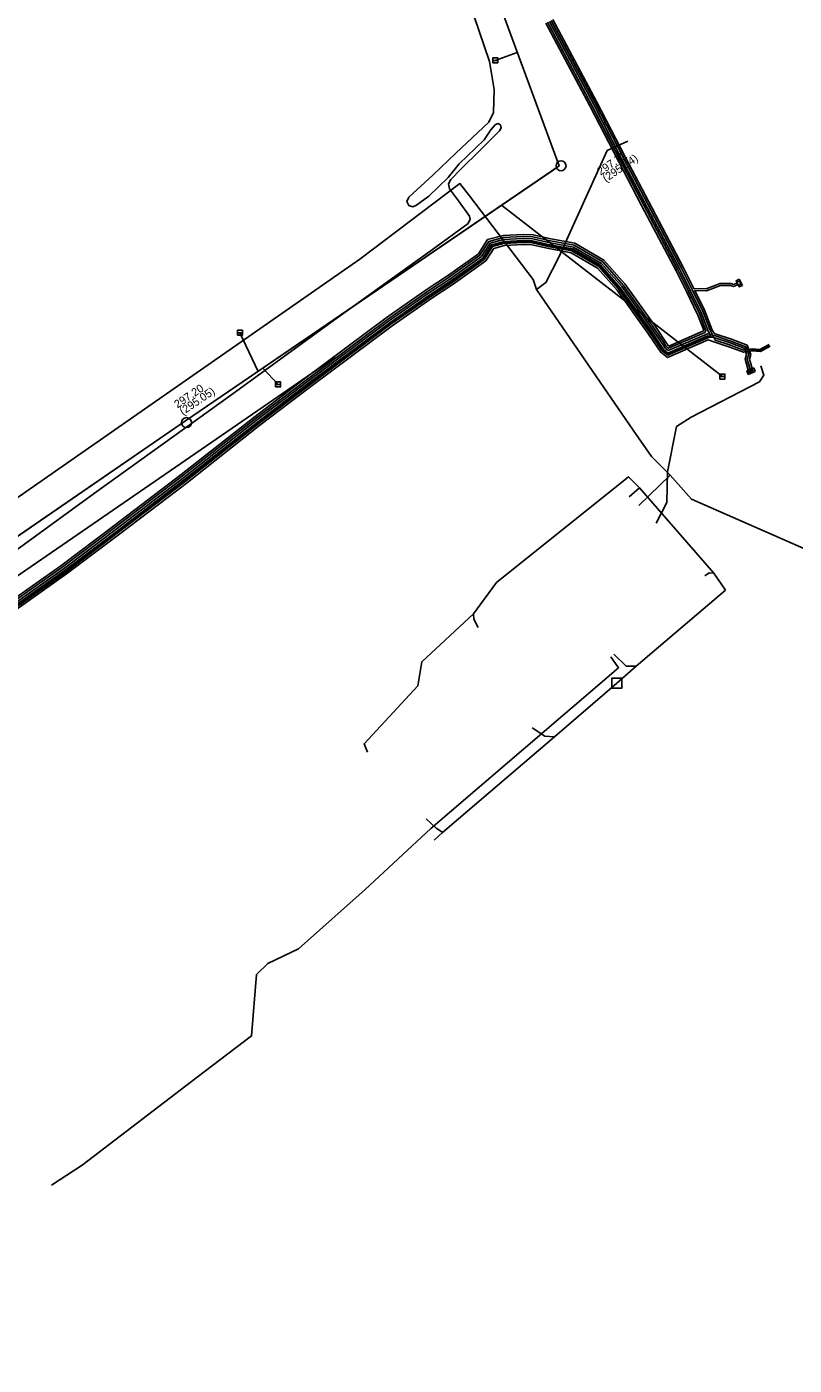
# Model space of a CAD drawing. Extents: x -600391 to -599491, y -1160176 to -1159402.
# Drawn here: x -599721.4 to -599644.7, y -1159814.7 to -1159680.9 of the extents above; entities that cross this region are included whole.
import ezdxf

# ---------------------------------------------------------------- set-up
doc = ezdxf.new("R2010")
doc.units = 0
for name, color, linetype in [('28', 7, 'Continuous'), ('31', 7, 'Continuous'), ('Vrstva 1', 7, 'Continuous'), ('Vrstva 11', 7, 'Continuous'), ('Vrstva 13', 7, 'Continuous'), ('Vrstva 19', 7, 'Continuous'), ('Vrstva 3', 7, 'Continuous'), ('Vrstva 4', 7, 'Continuous'), ('Vrstva 42', 7, 'Continuous'), ('Vrstva 43', 7, 'Continuous'), ('Vrstva 44', 7, 'Continuous'), ('Vrstva 58', 7, 'Continuous'), ('Vrstva 9', 7, 'Continuous')]:
    doc.layers.add(name, color=color, linetype=linetype)

# ---------------------------------------------------------------- blocks, each defined once
blk = doc.blocks.new('NN630')
at = {"layer": '31'}
for points in [[(0, -0.7), (-0.7, 0)], [(-0.7, -0.7), (-0.7, 0), (0.7, 0), (0.7, -0.7)], [(-0.7, -0.7), (0.7, -0.7)], [(0, -0.7), (0.7, 0)]]:
    blk.add_lwpolyline(points, dxfattribs=at)
blk = doc.blocks.new('NN620')
at = {"layer": '28'}
for points in [[(0.75, 0), (-0.75, 0)], [(-0.75, 0), (-0.75, -0.75)], [(0.75, -0.75), (0.75, 0)], [(-0.75, -0.75), (0.75, -0.75)], [(0.37, -0.18), (-0.38, -0.18)], [(-0.38, -0.18), (-0.38, -0.56)], [(-0.38, -0.56), (0.37, -0.56)], [(0.32, -0.23), (-0.33, -0.23)], [(-0.33, -0.23), (-0.33, -0.51)], [(-0.33, -0.51), (0.32, -0.51)], [(0.27, -0.27), (-0.28, -0.27)], [(-0.28, -0.27), (-0.28, -0.46)], [(-0.28, -0.46), (0.27, -0.46)], [(0.23, -0.32), (-0.23, -0.32)], [(-0.23, -0.32), (-0.23, -0.42)], [(-0.23, -0.42), (0.23, -0.42)], [(-0.19, -0.37), (0.19, -0.37)], [(0.23, -0.42), (0.23, -0.32)], [(0.27, -0.46), (0.27, -0.27)], [(0.32, -0.51), (0.32, -0.23)], [(0.37, -0.56), (0.37, -0.18)]]:
    blk.add_lwpolyline(points, dxfattribs=at)

msp = doc.modelspace()

# ---------------------------------------------------------------- linework, layer by layer
at = {"layer": 'Vrstva 1'}
for p, q in [((-599674.58, -1159684.31), (-599672.38, -1159683.53)), ((-599651.88, -1159715.91), (-599673.97, -1159698.78)), ((-599700.11, -1159711.53), (-599698.3, -1159715.39)), ((-599696.3, -1159716.69), (-599697.81, -1159715.05))]:
    msp.add_line(p, q, dxfattribs=at)
for points in [[(-599733.6, -1159557.62), (-599719.6, -1159585.05), (-599698.44, -1159625.81), (-599676.83, -1159671.44), (-599668.21, -1159694.85), (-599705.56, -1159720.34), (-599743.19, -1159746.17), (-599779.24, -1159770.44), (-599816.43, -1159796.74)], [(-599668.21, -1159694.85), (-599676.83, -1159671.44)], [(-599672.38, -1159683.53), (-599674.58, -1159684.31)], [(-599705.56, -1159720.34), (-599668.91, -1159695.33), (-599668.21, -1159694.85)], [(-599673.97, -1159698.78), (-599651.88, -1159715.91)], [(-599698.3, -1159715.39), (-599700.11, -1159711.53)], [(-599690.59, -1159713.98), (-599695.76, -1159717.54), (-599765.8, -1159765.71)], [(-599697.81, -1159715.05), (-599696.3, -1159716.69)], [(-599743.19, -1159746.17), (-599725.14, -1159733.78), (-599705.56, -1159720.34)]]:
    msp.add_lwpolyline(points, dxfattribs=at)
at = {"layer": 'Vrstva 11'}
msp.add_lwpolyline([(-599662.92, -1159747.03), (-599661.92, -1159747.03), (-599661.92, -1159746.03), (-599662.92, -1159746.03)], close=True, dxfattribs=at)
at = {"layer": 'Vrstva 13'}
msp.add_lwpolyline([(-599718.93, -1159796.73), (-599715.87, -1159794.72), (-599704.39, -1159785.91), (-599698.94, -1159781.8), (-599698.46, -1159775.66), (-599697.31, -1159774.56), (-599694.25, -1159773.1), (-599687.6, -1159767.16), (-599681.04, -1159761.07), (-599662.26, -1159745), (-599663.05, -1159743.91)], dxfattribs=at)
at = {"layer": 'Vrstva 19'}
for points in [[(-599670.46, -1159707.2), (-599669.53, -1159706.51), (-599668.23, -1159703.97), (-599663.4, -1159693.32), (-599661.35, -1159692.39)], [(-599848.5, -1159814.71), (-599774.58, -1159764.38), (-599688.11, -1159704.16), (-599678.12, -1159696.61), (-599677.16, -1159697.83), (-599670.8, -1159706.19), (-599670.46, -1159707.2), (-599660.79, -1159721.25), (-599658.97, -1159723.88), (-599657.1, -1159725.77), (-599654.96, -1159728.17), (-599642.68, -1159733.56)], [(-599657.1, -1159725.77), (-599660.23, -1159728.79)]]:
    msp.add_lwpolyline(points, dxfattribs=at)
at = {"layer": 'Vrstva 3'}
for p, q in [((-599674.83, -1159684.31), (-599674.33, -1159684.31)), ((-599700.36, -1159711.53), (-599699.86, -1159711.53)), ((-599652.13, -1159715.91), (-599651.63, -1159715.91)), ((-599696.55, -1159716.69), (-599696.05, -1159716.69))]:
    msp.add_line(p, q, dxfattribs=at)
for points in [[(-599674.83, -1159684.56), (-599674.33, -1159684.56), (-599674.33, -1159684.06), (-599674.83, -1159684.06)], [(-599700.36, -1159711.78), (-599699.86, -1159711.78), (-599699.86, -1159711.28), (-599700.36, -1159711.28)], [(-599696.55, -1159716.94), (-599696.05, -1159716.94), (-599696.05, -1159716.44), (-599696.55, -1159716.44)], [(-599652.13, -1159716.16), (-599651.63, -1159716.16), (-599651.63, -1159715.66), (-599652.13, -1159715.66)]]:
    msp.add_lwpolyline(points, close=True, dxfattribs=at)
for centre in [(-599668.01, -1159694.84), (-599705.45, -1159720.51)]:
    msp.add_circle(centre, 0.5, dxfattribs=at)
at = {"layer": 'Vrstva 42'}
for points in [[(-599648.91, -1159715.11), (-599649.18, -1159714.18), (-599649.04, -1159713.69), (-599649.4, -1159712.76), (-599650.98, -1159712.16), (-599652.61, -1159711.62), (-599652.72, -1159711.58), (-599652.9, -1159711.27), (-599653.67, -1159709.28), (-599654.64, -1159707.3), (-599653.47, -1159707.32), (-599652.07, -1159706.81), (-599651.08, -1159706.81), (-599650.77, -1159706.91), (-599650.44, -1159706.78), (-599650.36, -1159706.64), (-599650.53, -1159706.6), (-599650.77, -1159706.69), (-599651.05, -1159706.61), (-599652.11, -1159706.61), (-599653.51, -1159707.12), (-599654.74, -1159707.1), (-599655.8, -1159704.97), (-599659.25, -1159698.43), (-599661.57, -1159694.02), (-599664.42, -1159688.47), (-599668.82, -1159680.23)], [(-599681.25, -1159707.56), (-599679.14, -1159706.18), (-599675.97, -1159703.92), (-599675.11, -1159702.57), (-599673.75, -1159702.21), (-599671.79, -1159702.12), (-599670.84, -1159702.14), (-599669.1, -1159702.54), (-599666.77, -1159702.96), (-599663.98, -1159704.6), (-599661.95, -1159706.9), (-599658.83, -1159711.24), (-599657.85, -1159712.7), (-599657.61, -1159713.06), (-599657.29, -1159713.31), (-599653.38, -1159711.62), (-599652.67, -1159711.81), (-599651.04, -1159712.35), (-599649.54, -1159712.92), (-599649.25, -1159713.7), (-599649.39, -1159714.18), (-599649.1, -1159715.19)], [(-599681.14, -1159707.73), (-599679.03, -1159706.35), (-599675.82, -1159704.06), (-599674.98, -1159702.74), (-599673.71, -1159702.41), (-599671.79, -1159702.32), (-599670.87, -1159702.34), (-599669.14, -1159702.73), (-599666.84, -1159703.15), (-599664.11, -1159704.75), (-599662.1, -1159707.03), (-599659, -1159711.35), (-599658.02, -1159712.81), (-599657.76, -1159713.2), (-599657.32, -1159713.55), (-599653.36, -1159711.83), (-599652.73, -1159712), (-599651.11, -1159712.54), (-599649.69, -1159713.08), (-599649.46, -1159713.71), (-599649.6, -1159714.18), (-599649.29, -1159715.27)], [(-599725.64, -1159740.68), (-599717.79, -1159735.15), (-599712.48, -1159731.15), (-599705.72, -1159726), (-599698.47, -1159720.29), (-599693.37, -1159716.41), (-599685.25, -1159710.36), (-599681.25, -1159707.56)], [(-599725.53, -1159740.85), (-599717.67, -1159735.31), (-599712.36, -1159731.31), (-599705.6, -1159726.16), (-599698.35, -1159720.45), (-599693.25, -1159716.57), (-599685.13, -1159710.52), (-599681.14, -1159707.73)], [(-599648.05, -1159714.83), (-599647.74, -1159715.76), (-599648.18, -1159716.44), (-599655.01, -1159719.95), (-599656.47, -1159720.9), (-599657.38, -1159725.43), (-599657.42, -1159728.5), (-599658.5, -1159730.54)]]:
    msp.add_lwpolyline(points, dxfattribs=at)
at = {"layer": 'Vrstva 44'}
for points in [[(-599655.82, -1159705.39), (-599655.98, -1159705.06), (-599661.75, -1159694.11), (-599664.6, -1159688.56), (-599669, -1159680.32)], [(-599656, -1159705.48), (-599656.16, -1159705.15), (-599661.93, -1159694.2), (-599664.78, -1159688.65), (-599669.18, -1159680.41)], [(-599725.47, -1159740.93), (-599717.61, -1159735.39), (-599712.3, -1159731.39), (-599705.54, -1159726.24), (-599698.29, -1159720.53), (-599693.19, -1159716.65), (-599685.07, -1159710.6), (-599681.09, -1159707.81), (-599678.97, -1159706.43), (-599675.75, -1159704.13), (-599674.92, -1159702.83), (-599673.7, -1159702.51), (-599671.79, -1159702.42), (-599670.88, -1159702.44), (-599669.16, -1159702.83), (-599666.88, -1159703.25), (-599664.17, -1159704.83), (-599662.18, -1159707.09), (-599659.08, -1159711.41), (-599658.1, -1159712.87), (-599657.83, -1159713.27), (-599657.33, -1159713.66), (-599653.35, -1159711.93), (-599652.73, -1159712)], [(-599725.41, -1159741.01), (-599717.55, -1159735.47), (-599712.24, -1159731.47), (-599705.48, -1159726.32), (-599698.23, -1159720.61), (-599693.13, -1159716.73), (-599685.01, -1159710.68), (-599681.03, -1159707.89), (-599678.91, -1159706.51), (-599675.68, -1159704.2), (-599674.86, -1159702.92), (-599673.69, -1159702.61), (-599671.79, -1159702.52), (-599670.89, -1159702.54), (-599669.18, -1159702.93), (-599666.92, -1159703.34), (-599664.23, -1159704.91), (-599662.26, -1159707.15), (-599659.16, -1159711.47), (-599658.18, -1159712.93), (-599657.9, -1159713.34), (-599657.35, -1159713.78), (-599653.34, -1159712.03), (-599652.99, -1159711.94), (-599653.26, -1159711.43), (-599654.03, -1159709.44), (-599655.09, -1159707.29), (-599656, -1159705.48)], [(-599725.3, -1159741.18), (-599717.43, -1159735.63), (-599712.12, -1159731.63), (-599705.36, -1159726.48), (-599698.11, -1159720.77), (-599693.01, -1159716.89), (-599684.89, -1159710.84), (-599680.92, -1159708.06), (-599678.8, -1159706.68), (-599675.53, -1159704.34), (-599674.73, -1159703.09), (-599673.65, -1159702.81), (-599671.79, -1159702.72), (-599670.92, -1159702.74), (-599669.22, -1159703.12), (-599666.99, -1159703.54), (-599664.36, -1159705.06), (-599662.41, -1159707.28), (-599659.33, -1159711.58), (-599658.35, -1159713.04), (-599658.05, -1159713.48), (-599657.37, -1159714.01), (-599653.3, -1159712.24), (-599652.73, -1159712.42), (-599651.24, -1159712.92), (-599649.76, -1159713.48), (-599648.88, -1159713.32), (-599648.09, -1159713.39), (-599647.11, -1159712.87)], [(-599647.21, -1159712.69), (-599648.13, -1159713.19), (-599648.9, -1159713.12), (-599649.77, -1159713.26), (-599651.18, -1159712.73), (-599652.59, -1159712.26), (-599653.08, -1159711.35), (-599653.85, -1159709.36), (-599654.91, -1159707.2), (-599655.82, -1159705.39)], [(-599652.73, -1159712), (-599651.11, -1159712.54), (-599649.45, -1159713.17), (-599648.11, -1159713.29), (-599647.16, -1159712.78)]]:
    msp.add_lwpolyline(points, dxfattribs=at)
at = {"layer": 'Vrstva 58'}
for points in [[(-599677.23, -1159678.36), (-599675.17, -1159684.41), (-599674.71, -1159687.2), (-599674.76, -1159689.53), (-599675.23, -1159690.47), (-599678.54, -1159693.58), (-599680.81, -1159695.76), (-599683.24, -1159697.99), (-599683.41, -1159698.4), (-599683.24, -1159698.82), (-599682.83, -1159698.94), (-599682.46, -1159698.76), (-599681.21, -1159697.87), (-599679.3, -1159696), (-599678.21, -1159694.65), (-599675.7, -1159692.24), (-599675.03, -1159691.25), (-599674.61, -1159690.73), (-599674.32, -1159690.62), (-599674.05, -1159690.76), (-599674, -1159691.05), (-599674.16, -1159691.36), (-599676.1, -1159693.28), (-599678.02, -1159695.19), (-599679.04, -1159696.2), (-599679.25, -1159696.64), (-599679.17, -1159697.14), (-599678.27, -1159698.35), (-599677.17, -1159699.88), (-599677.09, -1159700.19), (-599677.29, -1159700.6), (-599680.87, -1159703.2), (-599685.34, -1159706.4), (-599691.26, -1159710.68), (-599700.93, -1159717.68), (-599714.66, -1159727.57), (-599733.33, -1159741.14)], [(-599654.39, -1159709.62), (-599655.45, -1159707.47), (-599656.51, -1159705.33), (-599659.96, -1159698.8), (-599662.28, -1159694.39), (-599665.13, -1159688.84), (-599669.53, -1159680.59)], [(-599654.21, -1159709.54), (-599655.27, -1159707.38), (-599656.34, -1159705.24), (-599659.78, -1159698.71), (-599662.11, -1159694.29), (-599664.95, -1159688.75), (-599669.36, -1159680.5)], [(-599657.52, -1159712.48), (-599658.5, -1159711.01), (-599661.63, -1159706.65), (-599663.72, -1159704.28), (-599666.63, -1159702.58), (-599669.02, -1159702.14), (-599670.79, -1159701.74), (-599671.8, -1159701.72), (-599673.81, -1159701.81), (-599675.36, -1159702.22), (-599676.27, -1159703.64), (-599679.36, -1159705.85), (-599681.48, -1159707.23), (-599685.48, -1159710.03), (-599693.61, -1159716.09), (-599698.72, -1159719.98), (-599705.97, -1159725.69), (-599712.72, -1159730.83), (-599718.02, -1159734.82), (-599725.87, -1159740.36)], [(-599657.68, -1159712.59), (-599658.67, -1159711.12), (-599661.79, -1159706.78), (-599663.85, -1159704.44), (-599666.7, -1159702.77), (-599669.06, -1159702.34), (-599670.82, -1159701.94), (-599671.8, -1159701.92), (-599673.78, -1159702.01), (-599675.24, -1159702.4), (-599676.12, -1159703.78), (-599679.25, -1159706.02), (-599681.37, -1159707.4), (-599685.36, -1159710.19), (-599693.49, -1159716.25), (-599698.6, -1159720.13), (-599705.85, -1159725.84), (-599712.6, -1159730.99), (-599717.9, -1159734.99), (-599725.76, -1159740.52)], [(-599657.69, -1159712.59), (-599657.46, -1159712.92), (-599657.26, -1159713.08), (-599653.63, -1159711.51), (-599653.53, -1159711.29), (-599654.21, -1159709.54)], [(-599654.4, -1159709.61), (-599653.75, -1159711.28), (-599653.78, -1159711.35), (-599657.23, -1159712.85), (-599657.31, -1159712.79), (-599657.52, -1159712.48)]]:
    msp.add_lwpolyline(points, dxfattribs=at)
at = {"layer": 'Vrstva 9'}
for points in [[(-599687.35, -1159753.44), (-599687.69, -1159752.6), (-599682.34, -1159746.81), (-599681.93, -1159744.43), (-599676.76, -1159739.61), (-599674.46, -1159736.48), (-599661.27, -1159725.94), (-599660.17, -1159727.01), (-599652.74, -1159735.54), (-599651.57, -1159737.26)], [(-599661.19, -1159727.93), (-599660.17, -1159727.01)], [(-599652.74, -1159735.54), (-599653.2, -1159735.51), (-599653.64, -1159735.81)], [(-599651.57, -1159737.26), (-599660.5, -1159744.86), (-599662.42, -1159746.53), (-599668.67, -1159751.91), (-599679.85, -1159761.48), (-599680.68, -1159762.25)], [(-599676.76, -1159739.61), (-599676.74, -1159740.16), (-599676.31, -1159740.99)], [(-599660.49, -1159744.86), (-599661.51, -1159744.86), (-599662.74, -1159743.64)], [(-599668.67, -1159751.91), (-599669.62, -1159751.83), (-599670.89, -1159751)], [(-599681.48, -1159760.12), (-599680.49, -1159761.05), (-599679.84, -1159761.48)]]:
    msp.add_lwpolyline(points, dxfattribs=at)

# ---------------------------------------------------------------- block references
at = {"layer": 'Vrstva 43'}
for name, p, xscale, yscale, rotation in [('NN630', (-599650.36, -1159706.64), 0.5, 0.5, 117), ('NN620', (-599649.1, -1159715.19), 0.5000000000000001, 0.4999999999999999, 23)]:
    msp.add_blockref(name, p, dxfattribs=dict(at, xscale=xscale, yscale=yscale, rotation=rotation))

# ---------------------------------------------------------------- texts
at = {"layer": 'Vrstva 4'}
for s, p in [('297.72', (-599664.06, -1159695.82)), ('(295.54)', (-599663.53, -1159696.51)), ('297.20', (-599706.35, -1159719.1)), ('(295.05)', (-599705.82, -1159719.79))]:
    msp.add_text(s, height=0.8, rotation=34.0134, dxfattribs=at).set_placement(p)

doc.saveas('drawing.dxf')
